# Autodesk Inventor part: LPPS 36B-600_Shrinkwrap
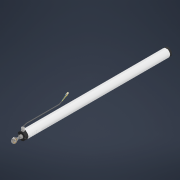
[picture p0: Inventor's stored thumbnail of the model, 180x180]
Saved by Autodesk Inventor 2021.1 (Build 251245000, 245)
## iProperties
Created: 2020-09
Part Number: LPPS 36B-600_Shrinkwrap
Material: Generic
Document SubType Name: Modeling
Designer: J. Nielson
Density: 1 g/cm^3
Appearance: Default
Author: J. Nielson
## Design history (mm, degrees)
derived "LPPS 36B-600.iam"
body "Solid1"
node "LPPS 36B Cable End Cap.iam:1::LPPS-36B PLASTIC CABLE END.ipt"
node "LPPS 36B Cable End Cap.iam:1::LPPS 36B- Cable Gland.ipt:1"
body "Solid2"
node "LPPS 36B Cable End Cap.iam:1::Cable Gland Cap.ipt:1"
body "Solid3"
node "LPPS 36B Cable End Cap.iam:1::Cable.ipt:1"
body "Solid4"
node "LPPS 36B Cable End Cap.iam:1::Cable Gland Seal 1 of 2.ipt:1"
body "Solid5"
node "LPPS 36B Cable End Cap.iam:1::Cable Gland 2 of 2.ipt:1"
body "Solid6"
node "LPPS 36B Cable End Cap.iam:1::#6 Terminal Ring 22 - 18 AWG.i"
body "Solid7"
node "LPPS-36B-600 METAL HOUSING.ipt:1"
body "Solid8"
node "MALE Rod Eye SW.ipt:1"
body "Solid9"
node "LPPS-36B PLASTIC STROKE END.ipt:1"
body "Solid10"
node "LPPS-36B-600 Back Stop.ipt:1"
body "Solid11"
node "LPPS-36B-600 Front Stop.ipt:1"
body "Solid12"
node "AS 1427 - M3 x 16.ipt:1"
body "Solid13"
node "AS 1427 - M3 x 16.ipt:2"
body "Solid14"
node "AS 1427 - M3 x 16.ipt:3"
body "Solid15"
node "AS 1427 - M3 x 16.ipt:4"
body "Solid16"
node "AS 1112 - M8  Type 5.ipt:1"
body "Solid17"
node "AS 1237 - 8.ipt:1"
body "Solid18"
node "AS 1968 - 1976 - 8.ipt:1"
body "Solid19"
